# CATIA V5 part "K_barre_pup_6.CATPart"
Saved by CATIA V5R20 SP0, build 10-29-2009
Part number: barre_pup_6
Bounding box of the stored display mesh (mm): x -51.426 to -49.394, y -211.469 to -6.5, z 33.474 to 42.045
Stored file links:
  G:\Khaled_CFAO_2011\ST2M\ST2M_GR2\gcausse\Khaled\CAD_ThinkMotion\K_barre_pup_6.CATPart
  C:\Documents and Settings\gcausse\Bureau\video thinkmotio\assemblage_gcausse\pupitre_think.CATProduct
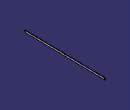
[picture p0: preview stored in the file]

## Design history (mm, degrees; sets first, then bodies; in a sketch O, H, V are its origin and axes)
Set1
  Sketch1 on Plane1, origin (-53.7378, 0, 6.6108), H (0, 1, 0), V (0.1221, 0, 0.9925)
    line L1 (-208.9252, 35.5784) -> (-8.9561, 32.0651)
    arc A1 centre (-9, 29.5654) radius 2.5 from (-8.9561, 32.0651) to (-9.0439, 27.0658) cw
    point P3 (-9, 29.5654)
    line L2 (-9.0439, 27.0658) -> (-209.0131, 30.5792)
    arc A2 centre (-208.9691, 33.0788) radius 2.5 from (-209.0131, 30.5792) to (-208.9252, 35.5784) cw
    point P6 (-208.9691, 33.0788)
    reference projected point E1 (-208.9691, 33.0788) from Point1
    reference projected point E2 (-9, 29.5654) from Point2
    reference projected line E3 (-9, 29.5654) -> (-208.9691, 33.0788) from Line1
    distance L1 L2 = 5
    tangency: A1 L1, L2 A1, A2 L1, A2 L2
    coincidence: P6 E1, P3 E2
    parallelism: L2 E3
Set2
  Plane1: linked copy from another document
  Point1: linked copy from another document
  Point2: linked copy from another document
  Line1: linked copy from another document
Body1 (main body)
  Pad1: profile Sketch1, direction (0.9925, 0, -0.1221), length -1
  Sketch2 on end face of Pad1, origin (-51.0584, -112.2065, 36.5815), H (0.1221, 0, 0.9925), V (0, 1, 0)
    point P1 (-0.5081, 103.2065)
    reference projected point E1 (-0.5081, 103.2065) from Point2
    coincidence: P1 E1
  Hole1: placed by Sketch2, at (-51.1204, -9, 36.0771) direction (0.9925, 0, -0.1221), diameter 1, depth 1
  Sketch3 on end face of Pad1, origin (-51.0326, -106.8691, 36.7915), H (0.1221, 0, 0.9925), V (0, 1, 0)
    point P1 (2.7936, -102.1001)
    reference projected point E1 (2.7936, -102.1001) from Point1
    coincidence: P1 E1
  Hole2: placed by Sketch3, at (-50.6915, -208.9691, 39.5642) direction (0.9925, 0, -0.1221), diameter 1, depth 1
